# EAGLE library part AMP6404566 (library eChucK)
AMP 6404566 power supply connector
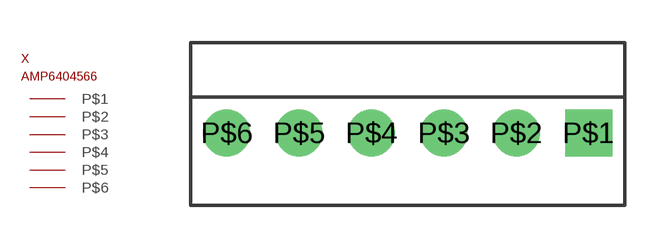
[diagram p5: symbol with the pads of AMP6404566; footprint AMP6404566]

Designator prefix X

## AMP6404566  [AMP6404566]
P$1  P$1
P$2  P$2
P$3  P$3
P$4  P$4
P$5  P$5
P$6  P$6

## Footprint AMP6404566 (pad centres in mm)
drill 1.1 square: P$1 6.35,0
drill 1.1 round: P$2 3.81,0; P$3 1.27,0; P$4 -1.27,0; P$5 -3.81,0; P$6 -6.35,0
